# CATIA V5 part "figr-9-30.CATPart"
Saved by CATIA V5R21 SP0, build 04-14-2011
Part number: Part1
Bounding box of the stored display mesh (mm): x -40 to 40, y -41.231 to 41.231, z -41.231 to 41.231
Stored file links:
  D:\CATIA V5R21 E-RESOURCES\CATIA-V5R21\catia-v5r21-prt\c09-catia-v5r20-prt\c09-catia-v5r21-figr-9-30.CATPart
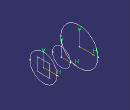
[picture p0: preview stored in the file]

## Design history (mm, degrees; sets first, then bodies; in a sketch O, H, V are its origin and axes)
Body1 (main body)
  Sketch1 on yz-plane, origin (0, 0, 0), H (0, 1, 0), V (0, 0, 1)
    circle A1 centre (0, 0) radius 20
  Plane1: type Offset, RefPlane yz-plane, Offset 40
  Plane2: type Offset, RefPlane yz-plane, Offset -40
  Sketch2 on Plane1, origin (40, 0, 0), H (0, 1, 0), V (0, 0, 1)
    circle A1 centre (0, 0) radius 30
  Sketch3 on Plane2, origin (-40, 0, 0), H (0, 1, 0), V (0, 0, 1)
    circle A1 centre (0, 0) radius 41.2311
  Loft1: solid, Sections (Sketch2; Sketch1; Sketch3)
